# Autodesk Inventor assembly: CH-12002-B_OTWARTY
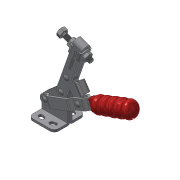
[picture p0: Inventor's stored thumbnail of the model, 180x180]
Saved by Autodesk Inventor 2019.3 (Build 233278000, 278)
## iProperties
Company: Î¢ÈíÖÐ¹ú
Created: 2012-09
Part Number: CH-12002-B_OTWARTY
Material: Ogólny
Description: STEP AP203
Document SubType Name: Assembly
Designer: CADENGINEERING4
Sending System: SolidWorks 2010
Preprocessor: SwSTEP 2.0
Title: CH-12002-B.STEP
Author: Î¢ÈíÓÃ»§
Revision Number: ÈÎºÎ
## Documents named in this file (10)
- D:\Vault_2016\Projekty\NASZ KATALOG\CLAMPTEK\STRONA\Vertical toggle clamp\CH-12002-B\CH-12002-B_OTWARTY.iam
- D:\Vault_2016\Projekty\NASZ KATALOG\CLAMPTEK\STEP FILES\Vertical toggle clamp\CH-12002-B\M6 Nut.ipt
- D:\Vault_2016\Projekty\NASZ KATALOG\CLAMPTEK\STEP FILES\Vertical toggle clamp\CH-12002-B\CH-12002-B-02 U-BAR.ipt
- D:\Vault_2016\Projekty\NASZ KATALOG\CLAMPTEK\STEP FILES\Vertical toggle clamp\CH-12002-B\CH-12002-B-06.ipt
- D:\Vault_2016\Projekty\NASZ KATALOG\CLAMPTEK\STEP FILES\Vertical toggle clamp\CH-12002-B\CH-12002-B-01 FLANGED BASE.ipt
- D:\Vault_2016\Projekty\NASZ KATALOG\CLAMPTEK\STEP FILES\Vertical toggle clamp\CH-12002-B\CH-FW-140.ipt
- D:\Vault_2016\Projekty\NASZ KATALOG\CLAMPTEK\STEP FILES\Vertical toggle clamp\CH-12002-B\CH-SA-064010 SPINDLE SUPPLIED.ipt
- D:\Vault_2016\Projekty\NASZ KATALOG\CLAMPTEK\STEP FILES\Vertical toggle clamp\CH-12002-B\CH-12002-B-07.ipt
- D:\Vault_2016\Projekty\NASZ KATALOG\CLAMPTEK\STEP FILES\Vertical toggle clamp\CH-12002-B\CH-12002-B-04 CONNECTING-PLATE.ipt
- D:\Vault_2016\Projekty\NASZ KATALOG\CLAMPTEK\STEP FILES\Vertical toggle clamp\CH-12002-B\CH-12002-B-03 HANDLE.ipt
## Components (14 placed, 9 different names)
1. CH-12002-B-01 FLANGED BASE_4
2. M6 Nut:3 — Zestawiające:2, Zestawiające:3, Zestawiające:4, Zestawiające:7, Zestawiające:24, Zestawiające:25, Zestawiające:26
3. CH-12002-B-02 U-BAR:2 — Zestawiające:5, Zestawiające:6, Zestawiające:12, Zestawiające:13, Zestawiające:15, Zestawiające:16, Zestawiające:20, Zestawiające:21, Zestawiające:22, Zestawiające:23, Zestawiające:24, Zestawiające:25, Zestawiające:26, Kątowe:1
4. CH-12002-B-06:5 — Zestawiające:20, Zestawiające:21, Zestawiające:22
5. M6 Nut:4 — Zestawiające:1, Zestawiające:8
6. CH-FW-140:3 — Zestawiające:3, Zestawiające:6, Zestawiające:7, Równoległe:1, Kątowe:1
7. CH-SA-064010 SPINDLE SUPPLIED:2 — Zestawiające:1, Zestawiające:2
8. CH-12002-B-07:2 — Zestawiające:27, Zestawiające:28, Zestawiające:29
9. CH-12002-B-06:6 — Zestawiające:9, Zestawiające:10, Zestawiające:11
10. CH-12002-B-04 CONNECTING-PLATE:2 — Zestawiające:14, Zestawiające:15, Zestawiające:17, Zestawiające:31
11. CH-FW-140:4 — Zestawiające:4, Zestawiające:5, Zestawiające:8, Równoległe:1
12. CH-12002-B-06:7 — Zestawiające:12, Zestawiające:13, Zestawiające:14, Zestawiające:16, Zestawiające:23
13. CH-12002-B-06:8 — Zestawiające:18, Zestawiające:19, Zestawiające:31
14. CH-12002-B-03 HANDLE:2 — Zestawiające:9, Zestawiające:10, Zestawiające:11, Zestawiające:17, Zestawiające:18, Zestawiające:19, Zestawiające:27, Zestawiające:28, Zestawiające:29
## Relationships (32: Mate 30, Flush 1, Angle 1)
- Zestawiające:1 [Mate]: M6 Nut:4 ↔ CH-SA-064010 SPINDLE SUPPLIED:2
- Zestawiające:2 [Mate]: M6 Nut:3 ↔ CH-SA-064010 SPINDLE SUPPLIED:2
- Zestawiające:3 [Mate]: M6 Nut:3 ↔ CH-FW-140:3
- Zestawiające:4 [Mate]: M6 Nut:3 ↔ CH-FW-140:4
- Zestawiające:5 [Mate]: CH-12002-B-02 U-BAR:2 ↔ CH-FW-140:4
- Zestawiające:6 [Mate]: CH-12002-B-02 U-BAR:2 ↔ CH-FW-140:3
- Zestawiające:7 [Mate]: M6 Nut:3 ↔ CH-FW-140:3
- Zestawiające:8 [Mate]: M6 Nut:4 ↔ CH-FW-140:4
- Zestawiające:9 [Mate]: CH-12002-B-06:6 ↔ CH-12002-B-03 HANDLE:2
- Zestawiające:10 [Mate]: CH-12002-B-06:6 ↔ CH-12002-B-03 HANDLE:2
- Zestawiające:11 [Mate]: CH-12002-B-06:6 ↔ CH-12002-B-03 HANDLE:2
- Zestawiające:12 [Mate]: CH-12002-B-02 U-BAR:2 ↔ CH-12002-B-06:7
- Zestawiające:13 [Mate]: CH-12002-B-02 U-BAR:2 ↔ CH-12002-B-06:7
- Zestawiające:14 [Mate]: CH-12002-B-04 CONNECTING-PLATE:2 ↔ CH-12002-B-06:7
- Zestawiające:15 [Mate]: CH-12002-B-02 U-BAR:2 ↔ CH-12002-B-04 CONNECTING-PLATE:2
- Zestawiające:16 [Mate]: CH-12002-B-02 U-BAR:2 ↔ CH-12002-B-06:7
- Zestawiające:17 [Mate]: CH-12002-B-04 CONNECTING-PLATE:2 ↔ CH-12002-B-03 HANDLE:2
- Zestawiające:18 [Mate]: CH-12002-B-06:8 ↔ CH-12002-B-03 HANDLE:2
- Zestawiające:19 [Mate]: CH-12002-B-06:8 ↔ CH-12002-B-03 HANDLE:2
- Zestawiające:20 [Mate]: CH-12002-B-02 U-BAR:2 ↔ CH-12002-B-06:5
- Zestawiające:21 [Mate]: CH-12002-B-02 U-BAR:2 ↔ CH-12002-B-06:5
- Zestawiające:22 [Mate]: CH-12002-B-02 U-BAR:2 ↔ CH-12002-B-06:5
- Zestawiające:23 [Mate]: CH-12002-B-02 U-BAR:2 ↔ CH-12002-B-06:7
- Zestawiające:24 [Mate]: M6 Nut:3 ↔ CH-12002-B-02 U-BAR:2
- Zestawiające:25 [Mate]: M6 Nut:3 ↔ CH-12002-B-02 U-BAR:2
- Zestawiające:26 [Mate]: M6 Nut:3 ↔ CH-12002-B-02 U-BAR:2
- Zestawiające:27 [Mate]: CH-12002-B-07:2 ↔ CH-12002-B-03 HANDLE:2
- Zestawiające:28 [Mate]: CH-12002-B-07:2 ↔ CH-12002-B-03 HANDLE:2
- Zestawiające:29 [Mate]: CH-12002-B-07:2 ↔ CH-12002-B-03 HANDLE:2
- Równoległe:1 [Flush]: CH-FW-140:3 ↔ CH-FW-140:4
- Kątowe:1 [Angle]: CH-12002-B-02 U-BAR:2 ↔ CH-FW-140:3
- Zestawiające:31 [Mate]: CH-12002-B-04 CONNECTING-PLATE:2 ↔ CH-12002-B-06:8
